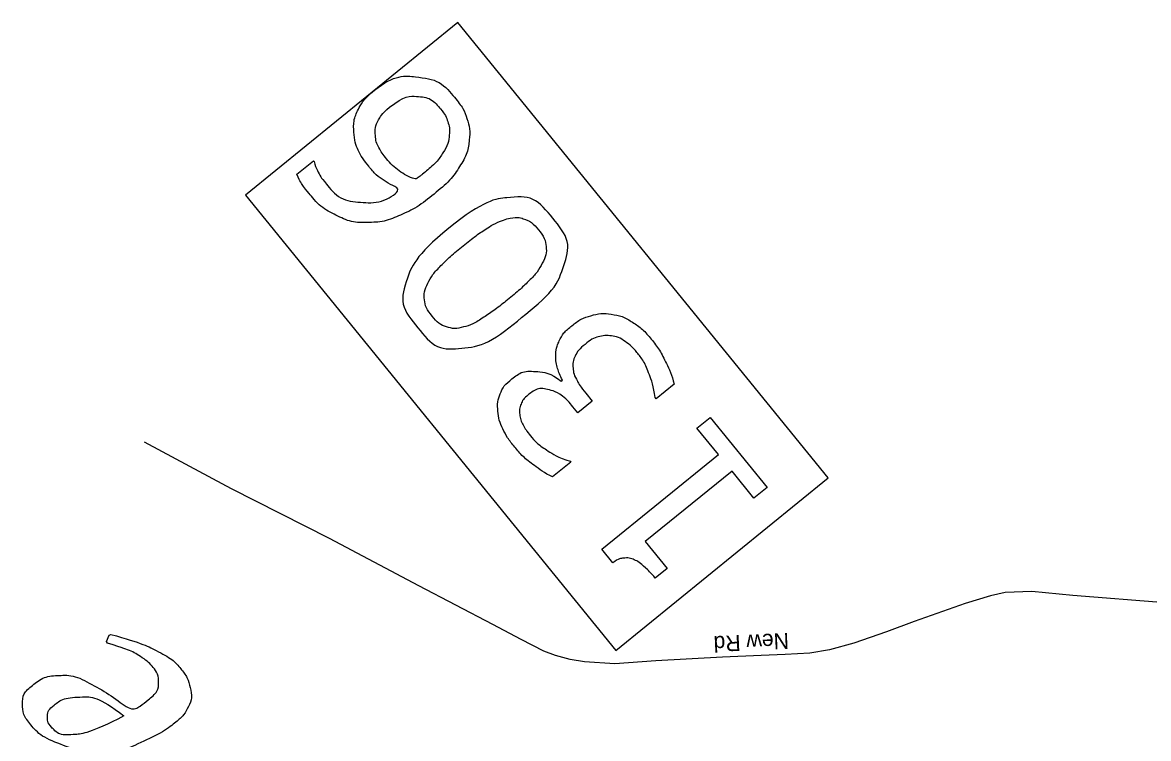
# Model space of a CAD drawing. Extents: x 2596159 to 2598075, y 851667 to 853493.
# Drawn here: x 2597029.92 to 2597077.48, y 851968.45 to 851998.71 of the extents above; entities that cross this region are included whole.
import ezdxf

# ---------------------------------------------------------------- set-up
doc = ezdxf.new("R2010")
doc.units = 0
doc.layers.add('Old_Level_1', color=7, linetype='Continuous')

msp = doc.modelspace()

# ---------------------------------------------------------------- linework, layer by layer
at = {"layer": 'Old_Level_1'}
for p, q in [((2597063.95, 851979.466), (2597048.31, 851998.709)), ((2597036.993, 851979.948), (2597035.071, 851980.97)), ((2597038.754, 851979.008), (2597036.993, 851979.948)), ((2597042.884, 851976.899), (2597038.754, 851979.008)), ((2597046.66, 851974.909), (2597042.884, 851976.899)), ((2597049.79, 851973.27), (2597046.66, 851974.909)), ((2597070.808, 851974.487), (2597069.731, 851974.153)), ((2597071.424, 851974.624), (2597070.808, 851974.487)), ((2597072.551, 851974.668), (2597071.424, 851974.624)), ((2597074.284, 851974.503), (2597072.551, 851974.668)), ((2597078.181, 851974.181), (2597074.284, 851974.503)), ((2597069.731, 851974.153), (2597067.574, 851973.392)), ((2597050.982, 851972.639), (2597049.79, 851973.27)), ((2597067.574, 851973.392), (2597066.417, 851972.96)), ((2597066.417, 851972.96), (2597065.026, 851972.477)), ((2597051.94, 851972.148), (2597050.982, 851972.639)), ((2597065.026, 851972.477), (2597064.009, 851972.199)), ((2597052.437, 851971.963), (2597051.94, 851972.148)), ((2597053.054, 851971.789), (2597052.437, 851971.963)), ((2597059.482, 851971.898), (2597056.669, 851971.732)), ((2597061.114, 851971.955), (2597059.482, 851971.898)), ((2597062.13, 851972.007), (2597061.114, 851971.955)), ((2597063.17, 851972.06), (2597062.13, 851972.007)), ((2597064.009, 851972.199), (2597063.17, 851972.06)), ((2597053.649, 851971.691), (2597053.054, 851971.789)), ((2597054.939, 851971.616), (2597053.649, 851971.691)), ((2597056.669, 851971.732), (2597054.939, 851971.616))]:
    msp.add_line(p, q, dxfattribs=at)
for points in [[(2597063.95, 851979.466), (2597048.31, 851998.709), (2597039.341, 851991.42), (2597054.981, 851972.176), (2597063.95, 851979.466)], [(2597041.505, 851992.296), (2597042.21, 851992.87), (2597042.24, 851992.833)], [(2597052.675, 851983.548), (2597052.726, 851983.589)], [(2597057.446, 851983.425), (2597056.679, 851982.802), (2597056.634, 851982.857)], [(2597053.714, 851983.04), (2597053.983, 851982.708), (2597053.376, 851982.215), (2597053.166, 851982.472)], [(2597054.847, 851975.881), (2597054.384, 851976.45), (2597059.313, 851980.456), (2597058.406, 851981.572), (2597058.964, 851982.025)], [(2597058.964, 851982.025), (2597061.369, 851979.066), (2597060.811, 851978.612), (2597059.886, 851979.75), (2597056.221, 851976.772), (2597057.146, 851975.633), (2597056.646, 851975.227)], [(2597053.045, 851980.168), (2597053.075, 851980.132), (2597052.308, 851979.509)], [(2597033.475, 851972.547), (2597033.584, 851972.822), (2597033.654, 851972.855)], [(2597033.514, 851972.489), (2597033.475, 851972.547)]]:
    msp.add_lwpolyline(points, dxfattribs=at)
for points in [[(2597044.788, 851995.847), (2597045.622, 851996.524), (2597046.595, 851996.404), (2597047.568, 851996.283), (2597048.216, 851995.486), (2597048.544, 851995.082), (2597048.688, 851994.65), (2597048.832, 851994.218), (2597048.791, 851993.765), (2597048.743, 851993.201), (2597048.378, 851992.621), (2597048.014, 851992.041), (2597047.305, 851991.465), (2597046.577, 851990.874), (2597045.888, 851990.573), (2597045.199, 851990.272), (2597044.484, 851990.259), (2597043.807, 851990.245), (2597043.158, 851990.566), (2597042.51, 851990.887), (2597041.958, 851991.566), (2597041.781, 851991.783), (2597041.68, 851991.945), (2597041.579, 851992.107), (2597041.505, 851992.296)], [(2597042.24, 851992.833), (2597042.268, 851992.685), (2597042.386, 851992.437), (2597042.504, 851992.189), (2597042.68, 851991.972), (2597043.321, 851991.183), (2597044.197, 851991.115), (2597045.072, 851991.047), (2597045.976, 851991.653), (2597045.538, 851991.809), (2597045.198, 851992.029), (2597044.857, 851992.249), (2597044.538, 851992.641), (2597044.255, 851992.99), (2597044.103, 851993.308), (2597043.951, 851993.626), (2597043.92, 851994.063), (2597043.881, 851994.568), (2597044.09, 851995.009), (2597044.299, 851995.45), (2597044.788, 851995.847)], [(2597045.426, 851995.127), (2597045.085, 851994.85), (2597044.943, 851994.567), (2597044.801, 851994.285), (2597044.824, 851993.92), (2597044.844, 851993.656), (2597044.974, 851993.421), (2597045.104, 851993.185), (2597045.286, 851992.962), (2597045.539, 851992.65), (2597045.83, 851992.442), (2597046.121, 851992.234), (2597046.504, 851992.077), (2597046.591, 851992.135), (2597046.669, 851992.193), (2597046.747, 851992.25), (2597046.861, 851992.342), (2597047.44, 851992.813), (2597047.679, 851993.205), (2597047.918, 851993.597), (2597047.942, 851993.964), (2597047.967, 851994.264), (2597047.882, 851994.521), (2597047.798, 851994.778), (2597047.61, 851995.009), (2597047.178, 851995.541), (2597046.606, 851995.581), (2597046.034, 851995.622), (2597045.426, 851995.127)], [(2597047.922, 851990.016), (2597049.397, 851991.215), (2597050.461, 851991.314), (2597051.525, 851991.414), (2597052.313, 851990.445), (2597053.113, 851989.461), (2597052.782, 851988.44), (2597052.452, 851987.419), (2597051.003, 851986.241), (2597049.543, 851985.054), (2597048.473, 851984.946), (2597047.403, 851984.839), (2597046.612, 851985.812), (2597045.813, 851986.796), (2597046.152, 851987.824), (2597046.492, 851988.853), (2597047.922, 851990.016)], [(2597050.377, 851990.407), (2597049.975, 851990.294), (2597049.535, 851990.012), (2597049.095, 851989.731), (2597048.528, 851989.27), (2597047.969, 851988.816), (2597047.595, 851988.436), (2597047.22, 851988.055), (2597047.041, 851987.69), (2597046.862, 851987.331), (2597046.899, 851986.992), (2597046.936, 851986.654), (2597047.219, 851986.305), (2597047.5, 851985.96), (2597047.827, 851985.851), (2597048.154, 851985.742), (2597048.552, 851985.846), (2597048.925, 851985.942), (2597049.4, 851986.252), (2597049.875, 851986.562), (2597050.397, 851986.986), (2597050.971, 851987.453), (2597051.324, 851987.807), (2597051.677, 851988.161), (2597051.875, 851988.541), (2597052.064, 851988.895), (2597052.034, 851989.24), (2597052.004, 851989.585), (2597051.706, 851989.952), (2597051.426, 851990.297), (2597051.097, 851990.408), (2597050.769, 851990.519), (2597050.377, 851990.407)], [(2597052.441, 851984.669), (2597052.456, 851984.974), (2597052.602, 851985.282), (2597052.749, 851985.59), (2597053.127, 851985.898), (2597053.502, 851986.202), (2597053.925, 851986.321), (2597054.348, 851986.439), (2597054.78, 851986.381), (2597055.261, 851986.315), (2597055.687, 851986.042), (2597056.113, 851985.769), (2597056.475, 851985.325), (2597056.845, 851984.87), (2597057.095, 851984.341), (2597057.345, 851983.812), (2597057.446, 851983.425)], [(2597056.634, 851982.857), (2597056.586, 851983.337), (2597056.378, 851983.87), (2597056.171, 851984.404), (2597055.851, 851984.797), (2597055.663, 851985.029), (2597055.373, 851985.227), (2597055.084, 851985.425), (2597054.801, 851985.464), (2597054.502, 851985.502), (2597054.239, 851985.426), (2597053.977, 851985.35), (2597053.678, 851985.107), (2597053.384, 851984.868), (2597053.267, 851984.617), (2597053.149, 851984.366), (2597053.174, 851984.11), (2597053.194, 851983.852), (2597053.343, 851983.582), (2597053.492, 851983.312), (2597053.714, 851983.04)], [(2597052.726, 851983.589), (2597052.612, 851983.79), (2597052.521, 851984.094), (2597052.43, 851984.397), (2597052.441, 851984.669)], [(2597052.308, 851979.509), (2597051.967, 851979.665), (2597051.505, 851980.013), (2597051.043, 851980.361), (2597050.711, 851980.769), (2597050.385, 851981.17), (2597050.211, 851981.534), (2597050.036, 851981.899), (2597049.998, 851982.277), (2597049.959, 851982.685), (2597050.098, 851983.024), (2597050.237, 851983.363), (2597050.572, 851983.635), (2597051.028, 851984.006), (2597051.629, 851983.96), (2597052.231, 851983.914), (2597052.675, 851983.548)], [(2597053.166, 851982.472), (2597052.712, 851983.031), (2597052.208, 851983.174), (2597051.704, 851983.317), (2597051.255, 851982.952), (2597051.056, 851982.79), (2597050.975, 851982.585), (2597050.895, 851982.379), (2597050.922, 851982.15), (2597050.955, 851981.914), (2597051.064, 851981.704), (2597051.174, 851981.494), (2597051.359, 851981.266), (2597051.643, 851980.917), (2597052.088, 851980.625), (2597052.533, 851980.333), (2597053.045, 851980.168)], [(2597056.646, 851975.227), (2597056.458, 851975.458), (2597056.205, 851975.691), (2597055.951, 851975.924), (2597055.767, 851976.001), (2597055.538, 851976.095), (2597055.318, 851976.077), (2597055.097, 851976.06), (2597054.847, 851975.881)], [(2597033.654, 851972.855), (2597034.963, 851972.492), (2597035.621, 851972.146), (2597036.279, 851971.801), (2597036.608, 851971.396), (2597036.898, 851971.039), (2597037, 851970.604), (2597037.103, 851970.168), (2597036.926, 851969.802), (2597036.75, 851969.435), (2597036.432, 851969.178), (2597035.905, 851968.749), (2597034.915, 851968.281), (2597033.925, 851967.813), (2597033.271, 851967.8), (2597032.617, 851967.787), (2597031.647, 851968.162), (2597030.677, 851968.537), (2597030.268, 851969.04), (2597029.923, 851969.465), (2597029.922, 851969.91), (2597029.921, 851970.356), (2597030.326, 851970.685), (2597030.824, 851971.09), (2597031.469, 851971.119), (2597032.114, 851971.149), (2597032.951, 851970.682), (2597033.789, 851970.215), (2597034.502, 851969.587), (2597034.902, 851969.823), (2597035.2, 851970.065), (2597035.679, 851970.454), (2597035.668, 851970.822), (2597035.656, 851971.19), (2597035.43, 851971.468), (2597035.267, 851971.668), (2597034.981, 851971.866), (2597034.695, 851972.063), (2597034.459, 851972.159), (2597034.223, 851972.255), (2597033.514, 851972.489)], [(2597034.202, 851969.408), (2597033.152, 851970.241), (2597032.395, 851970.21), (2597031.638, 851970.178), (2597031.228, 851969.845), (2597030.994, 851969.654), (2597030.975, 851969.412), (2597030.957, 851969.17), (2597031.12, 851968.97), (2597031.445, 851968.57), (2597032.106, 851968.62), (2597032.766, 851968.671), (2597034.202, 851969.408)]]:
    msp.add_open_spline(points, degree=3, dxfattribs=at)

# ---------------------------------------------------------------- texts
msp.add_text('New Rd', height=0.6695, rotation=182.4681, dxfattribs=at).set_placement((2597062.275, 851972.916))

doc.saveas('drawing.dxf')
